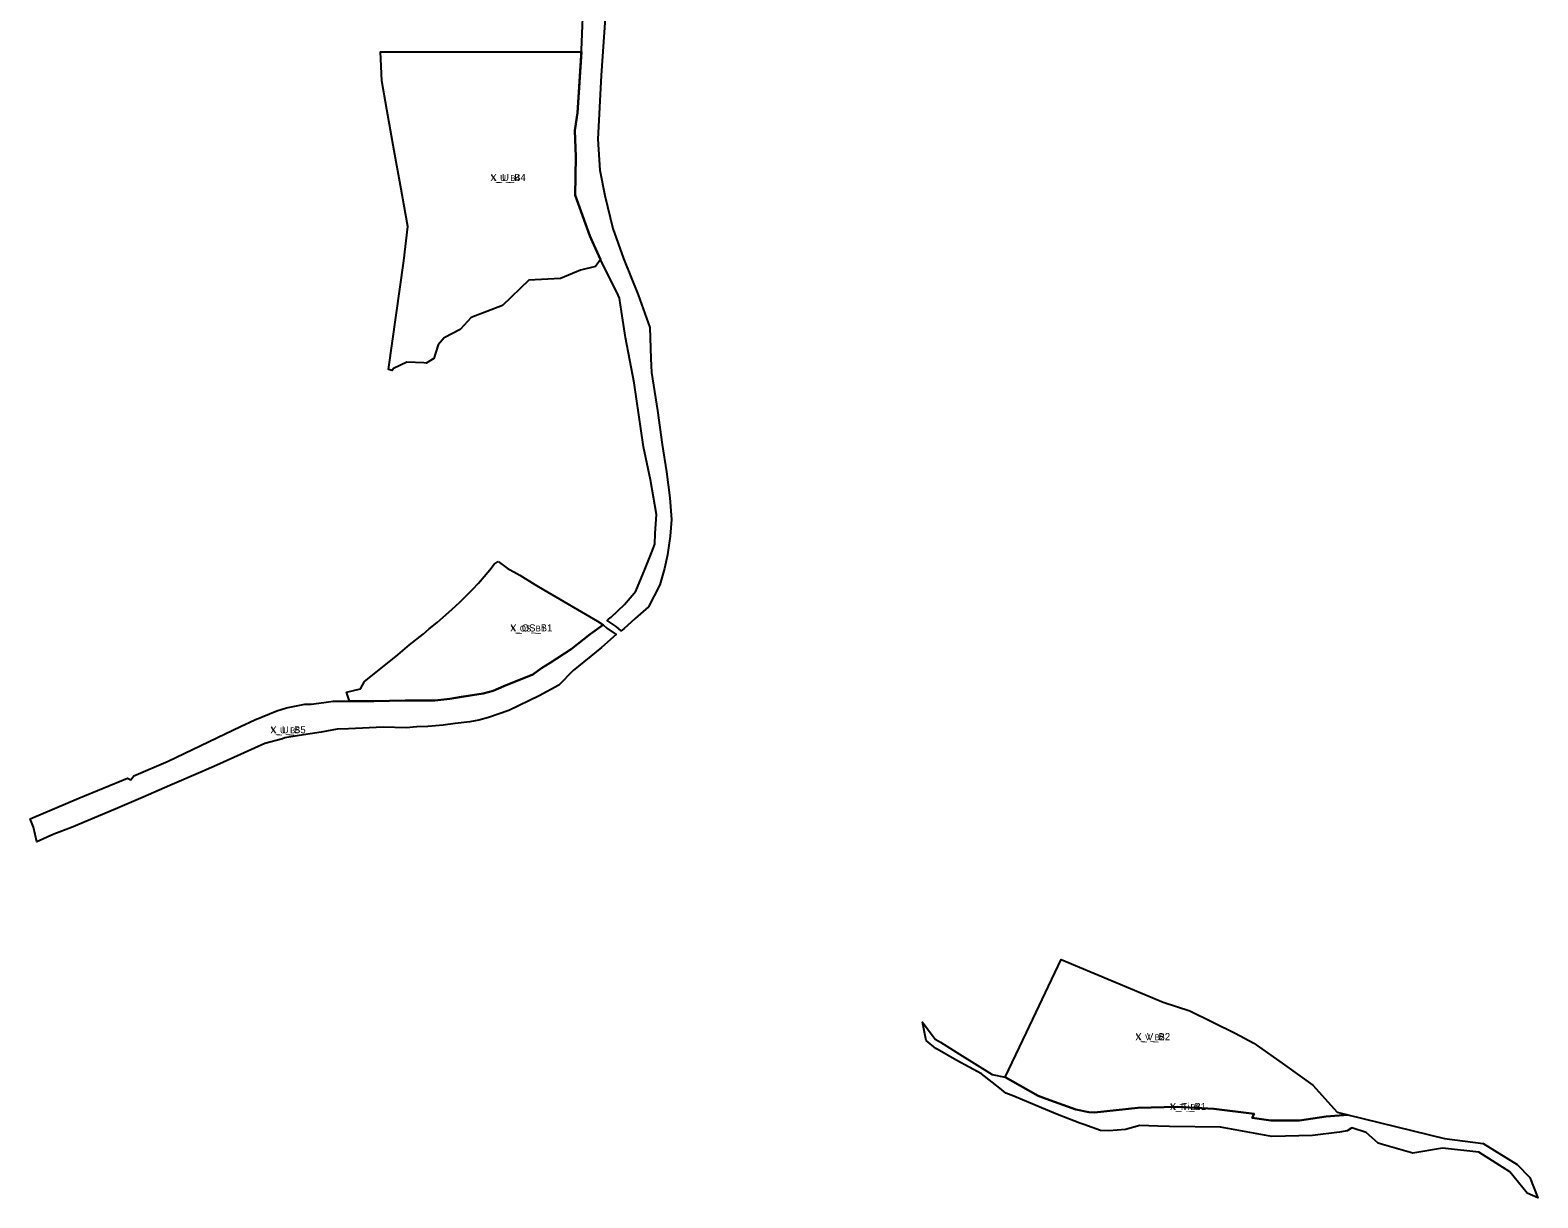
# Model space of a CAD drawing. Extents: x -532058 to -529750, y -1180391 to -1176703.
# Drawn here: x -531028 to -529750, y -1178538 to -1177548 of the extents above; entities that cross this region are included whole.
import ezdxf

# ---------------------------------------------------------------- set-up
doc = ezdxf.new("R2010")
doc.units = 0
for name, color, linetype in [('96120023', 7, 'Continuous'), ('96140023', 7, 'Continuous'), ('ID_VPO', 7, 'Continuous'), ('ID_VPS', 7, 'Continuous')]:
    doc.layers.add(name, color=color, linetype=linetype)

msp = doc.modelspace()

# ---------------------------------------------------------------- linework, layer by layer
at = {"layer": '96120023'}
msp.add_lwpolyline([(-529856.2, -1178500), (-529882, -1178492.6), (-529885.6, -1178491.3), (-529895.9, -1178482.4), (-529908.1, -1178478.5), (-529912, -1178481), (-529918.5, -1178482.1), (-529941.3, -1178484.9), (-529975.9, -1178485.8), (-530019.4, -1178477.9), (-530062.7, -1178477.3), (-530072.6, -1178476.9), (-530087.7, -1178476.4), (-530099.8, -1178479.8), (-530113.9, -1178480.9), (-530121, -1178480.6), (-530135.1, -1178475.6), (-530138.7, -1178474.3), (-530157.5, -1178467), (-530171, -1178461.3), (-530194.6, -1178451.6), (-530201.4, -1178448.9), (-530206.4, -1178444.9), (-530222, -1178432.5), (-530243, -1178421.2), (-530259.5, -1178411.8), (-530260.8, -1178411.1), (-530268.9, -1178404.4), (-530272, -1178388.9), (-530261.2, -1178403.2), (-530256.8, -1178405.9), (-530240.6, -1178416), (-530212.8, -1178433.3), (-530201.9, -1178435.4), (-530173.9, -1178451.3), (-530167.3, -1178453.7), (-530142, -1178462.8), (-530131, -1178465.1), (-530126.2, -1178465.3), (-530089.5, -1178461.5), (-530055.8, -1178460.7), (-530025, -1178462.4), (-529990.9, -1178466.5), (-529992.4, -1178470), (-529976.7, -1178472.3), (-529952.4, -1178472.1), (-529929.9, -1178468.9), (-529911.3, -1178467.4), (-529829.6, -1178487.4), (-529796.6, -1178491.6), (-529767.9, -1178509.6), (-529757.1, -1178520.5), (-529750.4, -1178537.7), (-529759.5, -1178533.9), (-529774.2, -1178515.7), (-529800.5, -1178499.1), (-529831.3, -1178495.6)], close=True, dxfattribs=at)
at = {"layer": '96140023'}
msp.add_lwpolyline([(-530541.1, -1177537.3), (-530544.3, -1177586.2), (-530547.3, -1177640.3), (-530545.4, -1177666.5), (-530541.4, -1177688.1), (-530534.4, -1177716.1), (-530525.4, -1177741.4), (-530513.1, -1177772.2), (-530503.2, -1177799.9), (-530502.3, -1177826.1), (-530501.7, -1177838.2), (-530496.5, -1177870.2), (-530492.6, -1177899.2), (-530489.1, -1177922.4), (-530486.2, -1177944.3), (-530484.9, -1177962.6), (-530486, -1177976.8), (-530488.2, -1177992.7), (-530490.7, -1178004.1), (-530494.7, -1178018.2), (-530504.4, -1178036.6), (-530515.6, -1178046.7), (-530525.3, -1178055.4), (-530527.4, -1178057), (-530531.8, -1178053.5), (-530536, -1178050.6), (-530539.2, -1178048.3), (-530538.2, -1178047.2), (-530535.8, -1178045.5), (-530524.5, -1178034.7), (-530515.1, -1178023.5), (-530507.5, -1178005), (-530501.7, -1177990.9), (-530498.9, -1177983.6), (-530498.5, -1177974.6), (-530497.5, -1177958.4), (-530502.6, -1177929), (-530508.4, -1177901.1), (-530516.4, -1177846.7), (-530523.7, -1177808.3), (-530527.1, -1177786.4), (-530528.8, -1177775), (-530531, -1177770.1), (-530543.1, -1177746.6), (-530544.9, -1177742.3), (-530550.5, -1177729.8), (-530554, -1177722.1), (-530566.3, -1177687.6), (-530565.8, -1177655.3), (-530566.6, -1177633), (-530564.5, -1177617.9), (-530561.1, -1177564.7), (-530559, -1177515.8)], dxfattribs=at)
for points in [[(-530726, -1177615.2), (-530730.3, -1177590.9), (-530731.6, -1177566.2), (-530561.2, -1177566.2), (-530564.5, -1177617.9), (-530566.6, -1177633), (-530565.8, -1177655.3), (-530566.3, -1177687.6), (-530554, -1177722.1), (-530550.5, -1177729.8), (-530544.9, -1177742.3), (-530549.1, -1177748.1), (-530561.8, -1177751.2), (-530578.9, -1177758.4), (-530605.7, -1177759.9), (-530628.1, -1177781.3), (-530654.6, -1177791.4), (-530664, -1177801.5), (-530677.6, -1177808.6), (-530682.6, -1177814.5), (-530686.2, -1177826.2), (-530692.7, -1177830.1), (-530694.6, -1177830), (-530709, -1177829.3), (-530720.4, -1177834.8), (-530721.5, -1177836.4), (-530724.8, -1177835.5), (-530711.7, -1177743.3), (-530708.4, -1177714.3), (-530714.6, -1177679.4), (-530719.8, -1177650.1)], [(-530631.7, -1177998.4), (-530624.2, -1178003.9), (-530613.4, -1178009.8), (-530600.6, -1178017.7), (-530592.9, -1178022.3), (-530547.4, -1178048.9), (-530542.7, -1178051.9), (-530553.6, -1178059.9), (-530569.9, -1178072.5), (-530587.6, -1178084.1), (-530595, -1178088.7), (-530602.3, -1178094.2), (-530626.8, -1178104.1), (-530636, -1178107.8), (-530644.4, -1178110.2), (-530653.6, -1178111.6), (-530663.2, -1178113.1), (-530672.8, -1178114.8), (-530685.4, -1178116.1), (-530698.7, -1178116.1), (-530710.6, -1178116.2), (-530737, -1178116.7), (-530757.7, -1178116.8), (-530760.2, -1178109.1), (-530748.4, -1178106.3), (-530745.1, -1178100.1), (-530725.6, -1178084.5), (-530716.8, -1178077.4), (-530706.9, -1178069), (-530695.3, -1178059.9), (-530690.2, -1178055.5), (-530683.5, -1178050), (-530678.4, -1178045.6), (-530670.9, -1178039), (-530664.3, -1178032.9), (-530658.8, -1178027.4), (-530653.2, -1178021.8), (-530648.5, -1178016.6), (-530643.6, -1178011), (-530638.9, -1178005.4), (-530635.1, -1178000.5)], [(-530597, -1178112.1), (-530622.7, -1178124.5), (-530640, -1178130.4), (-530648.1, -1178132.7), (-530655.8, -1178134.2), (-530668.1, -1178135.7), (-530678.2, -1178137.1), (-530691.4, -1178138.1), (-530700.6, -1178138.5), (-530709.8, -1178139.3), (-530729.2, -1178138.7), (-530758.7, -1178140.1), (-530768.3, -1178140.3), (-530781.7, -1178142.9), (-530800.3, -1178145.9), (-530812.6, -1178147.9), (-530814.6, -1178148.6), (-530829.6, -1178152.7), (-530855.8, -1178164.5), (-530870.1, -1178171), (-530883.9, -1178176.8), (-530910, -1178188.2), (-530932.6, -1178198.1), (-530956.4, -1178208.2), (-530993.4, -1178223.8), (-531008.4, -1178229.3), (-531022.7, -1178235.8), (-531025.7, -1178223.4), (-531028.5, -1178216.5), (-530987.1, -1178198.9), (-530946, -1178181.9), (-530943.2, -1178183.4), (-530940.7, -1178180), (-530911.6, -1178167.6), (-530863.2, -1178144.3), (-530850, -1178138.2), (-530838, -1178132.5), (-530819.3, -1178125), (-530811.1, -1178122.4), (-530795.5, -1178119.3), (-530790.3, -1178119.3), (-530779.6, -1178117.9), (-530771.5, -1178116.7), (-530757.7, -1178116.8), (-530737, -1178116.7), (-530710.6, -1178116.2), (-530685.4, -1178116.1), (-530672.8, -1178114.8), (-530653.6, -1178111.6), (-530644.4, -1178110.2), (-530636, -1178107.8), (-530626.8, -1178104.1), (-530602.3, -1178094.2), (-530595, -1178088.7), (-530587.6, -1178084.1), (-530569.9, -1178072.5), (-530553.6, -1178059.9), (-530542.7, -1178051.9), (-530539.7, -1178054.9), (-530531.7, -1178060.3), (-530544, -1178071.1), (-530568.1, -1178090.8), (-530580.4, -1178103.2)], [(-530055.8, -1178460.7), (-530089.5, -1178461.5), (-530126.2, -1178465.3), (-530131, -1178465.1), (-530142, -1178462.8), (-530167.3, -1178453.7), (-530173.9, -1178451.3), (-530201.9, -1178435.4), (-530183.8, -1178397.5), (-530154.4, -1178335.8), (-530067.9, -1178372), (-530045.5, -1178379.3), (-530007, -1178398.2), (-529991, -1178406.7), (-529965, -1178425.1), (-529941, -1178442.2), (-529920.6, -1178465.2), (-529911.3, -1178467.4), (-529929.9, -1178468.9), (-529952.4, -1178472.1), (-529976.7, -1178472.3), (-529992.4, -1178470), (-529990.9, -1178466.5), (-530025, -1178462.4)]]:
    msp.add_lwpolyline(points, close=True, dxfattribs=at)

# ---------------------------------------------------------------- texts
at = {"layer": '96120023'}
msp.add_text('X_Ti_B1', height=5, rotation=360, dxfattribs=at).set_placement((-530062.3, -1178463.3))
at = {"layer": '96140023'}
for s, rotation, p in [('X_U_B4', 360, (-530638.2, -1177675.7)), ('X_OS_B1', 0, (-530621.5, -1178057.6)), ('X_U_B5', 360, (-530824.8, -1178143.9)), ('X_V_B2', 360, (-530091.5, -1178404.1))]:
    msp.add_text(s, height=5, rotation=rotation, dxfattribs=at).set_placement(p)
at = {"layer": 'ID_VPO'}
for s, rotation, p in [('X_U_B4', 0, (-530638.2, -1177675.7)), ('X_OS_B1', 0, (-530621.5, -1178057.6)), ('X_U_B5', 0, (-530824.8, -1178143.9)), ('X_V_B2', 360, (-530091.5, -1178404.1))]:
    msp.add_text(s, height=6, rotation=rotation, dxfattribs=at).set_placement(p)
at = {"layer": 'ID_VPS'}
msp.add_text('X_Ti_B1', height=6, rotation=0, dxfattribs=at).set_placement((-530062.3, -1178463.3))

doc.saveas('drawing.dxf')
